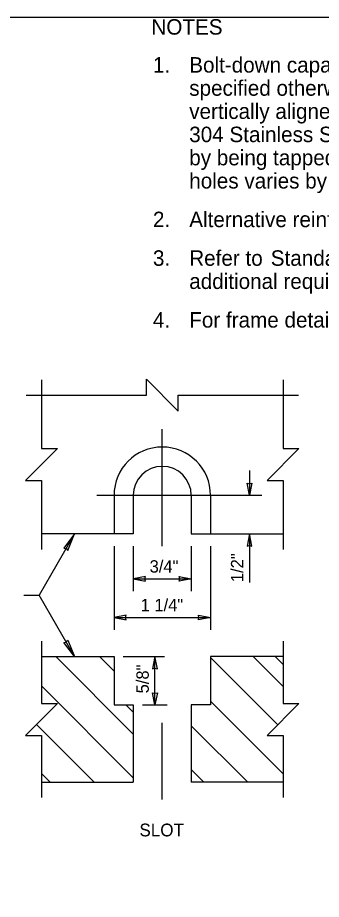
# Model space of a CAD drawing. Extents: x 99862 to 103151, y 100000 to 102076.
# Drawn here: x 101997 to 102390, y 100935 to 102076 of the extents above; entities that cross this region are included whole.
import ezdxf

# ---------------------------------------------------------------- set-up
doc = ezdxf.new("R2010")
doc.units = 0
for name, color, linetype in [('Level 1', 7, 'Continuous'), ('Level 15', 7, 'Continuous'), ('Level 17', 7, 'Continuous'), ('Level 2', 7, 'Continuous'), ('Level 20', 7, 'Continuous')]:
    doc.layers.add(name, color=color, linetype=linetype)

msp = doc.modelspace()

# ---------------------------------------------------------------- linework, layer by layer
at = {"layer": 'Level 1'}
msp.add_lwpolyline([(99862, 99999.5), (103151, 99999.5), (103151, 102075.5), (99862, 102075.5)], close=True, dxfattribs=at)
at = {"layer": 'Level 15'}
for p, q in [((102184.4, 101391.8), (102184.4, 101542.9)), ((102297.3, 101489.4), (102297.3, 101457.4)), ((102099.7, 101457.4), (102313.3, 101457.4)), ((102070.8, 101407.4), (102025, 101328.1)), ((102297.3, 101407.4), (102297.3, 101344.6)), ((102121.9, 101391.4), (102121.9, 101283.4)), ((102146.9, 101391.4), (102146.9, 101333.4)), ((102221.9, 101391.4), (102221.9, 101333.4)), ((102246.9, 101391.4), (102246.9, 101283.4)), ((102146.9, 101349.4), (102221.9, 101349.4)), ((102005, 101328.1), (102025, 101328.1)), ((102070.8, 101248.7), (102025, 101328.1)), ((102121.9, 101299.4), (102246.9, 101299.4)), ((102133.9, 101248.7), (102187.2, 101248.7)), ((102174.9, 101186.2), (102174.9, 101248.7)), ((102158.9, 101186.2), (102190.9, 101186.2)), ((102184.4, 101063.9), (102184.4, 101163.2))]:
    msp.add_line(p, q, dxfattribs=at)
for points in [[(102028.1, 101607), (102028.1, 101517.9), (102048.8, 101517.9), (102007.5, 101476.6), (102028.1, 101476.6), (102028.1, 101387.4)], [(102008.1, 101587), (102163.8, 101587), (102163.8, 101607.7), (102205.1, 101566.4), (102205.1, 101587), (102360.7, 101587)], [(102340.7, 101607), (102340.7, 101517.9), (102361.3, 101517.9), (102320, 101476.6), (102340.7, 101476.6), (102340.7, 101387.4)], [(102028.1, 101268.7), (102028.1, 101188.1), (102048.8, 101188.1), (102007.5, 101146.8), (102028.1, 101146.8), (102028.1, 101066.2)], [(102340.7, 101268.7), (102340.7, 101188.1), (102361.3, 101188.1), (102320, 101146.8), (102340.7, 101146.8), (102340.7, 101066.2)]]:
    msp.add_lwpolyline(points, dxfattribs=at)
for points in [[(102297.3, 101457.4), (102294.2, 101473.1), (102297.3, 101472.4), (102300.4, 101473.1)], [(102070.8, 101407.4), (102056.8, 101389.1), (102059.9, 101388.6), (102062, 101386.2)], [(102297.3, 101407.4), (102294.2, 101391.7), (102297.3, 101392.4), (102300.4, 101391.7)], [(102146.9, 101349.4), (102162.6, 101346.3), (102161.9, 101349.4), (102162.6, 101352.5)], [(102221.9, 101349.4), (102206.2, 101346.3), (102206.9, 101349.4), (102206.2, 101352.5)], [(102121.9, 101299.4), (102137.6, 101296.3), (102136.9, 101299.4), (102137.6, 101302.5)], [(102246.9, 101299.4), (102231.2, 101296.3), (102231.9, 101299.4), (102231.2, 101302.5)], [(102070.8, 101248.7), (102056.8, 101267), (102059.9, 101267.6), (102062, 101270)], [(102174.9, 101248.7), (102171.8, 101233), (102174.9, 101233.7), (102178, 101233)], [(102174.9, 101186.2), (102171.8, 101202), (102174.9, 101201.2), (102178, 101202)]]:
    msp.add_lwpolyline(points, close=True, dxfattribs=at)
at = {"layer": 'Level 17'}
for p, q in [((102146.9, 101148.5), (102046.6, 101248.7)), ((102121.9, 101230), (102103.2, 101248.7)), ((102333.8, 101160.6), (102246.9, 101247.4)), ((102340.7, 101210.2), (102302.2, 101248.7)), ((102340.7, 101238.5), (102330.4, 101248.7)), ((102146.9, 101091.9), (102028.1, 101210.7)), ((102340.7, 101097.1), (102246.9, 101190.9)), ((102146.9, 101176.8), (102137.4, 101186.2)), ((102096, 101086.2), (102021.5, 101160.8)), ((102295, 101086.2), (102221.9, 101159.3)), ((102039.4, 101086.2), (102028.1, 101097.5)), ((102238.4, 101086.2), (102221.9, 101102.7))]:
    msp.add_line(p, q, dxfattribs=at)
at = {"layer": 'Level 2'}
for p, q in [((102121.9, 101457.4), (102121.9, 101407.4)), ((102146.9, 101457.4), (102146.9, 101407.4)), ((102221.9, 101457.4), (102221.9, 101407.4)), ((102246.9, 101457.4), (102246.9, 101407.4)), ((102146.9, 101407.4), (102028.1, 101407.4)), ((102221.9, 101407.4), (102340.7, 101407.4)), ((102028.1, 101248.7), (102121.9, 101248.7)), ((102121.9, 101248.7), (102121.9, 101186.2)), ((102246.9, 101248.7), (102246.9, 101186.2)), ((102340.7, 101248.7), (102246.9, 101248.7)), ((102121.9, 101186.2), (102146.9, 101186.2)), ((102146.9, 101186.2), (102146.9, 101086.2)), ((102246.9, 101186.2), (102221.9, 101186.2)), ((102221.9, 101186.2), (102221.9, 101086.2)), ((102028.1, 101086.2), (102146.9, 101086.2)), ((102340.7, 101086.2), (102221.9, 101086.2))]:
    msp.add_line(p, q, dxfattribs=at)
for radius in [62.5, 37.5]:
    msp.add_arc((102184.4, 101457.4), radius, 360, 180, dxfattribs=at)

# ---------------------------------------------------------------- texts
at = {"layer": 'Level 1'}
msp.add_text('SLOT', height=16.5, dxfattribs=at).set_placement((102154.8, 101016.1))
at = {"layer": 'Level 20'}
for s, height, p in [('NOTES', 20, (102170.3, 102053.5)), ('1.', 20, (102172.3, 102004.4)), ('Bolt-down capability is required on all frames, grates, and covers, unless', 20, (102219.3, 102004.4)), ('specified otherwise in the Contract. Provide 2 holes in the frame that are', 20, (102219.3, 101974.4)), ('vertically aligned with the grate or cover slots. The frame shall accept the', 20, (102219.3, 101944.4)), ('304 Stainless Steel (S.S.) 5/8" (in) - 11 NC × 2" (in) allen head cap screw', 20, (102219.3, 101914.4)), ('by being tapped, or other approved mechanism. Location of bolt-down', 20, (102219.3, 101884.4)), ('holes varies by manufacturer.', 20, (102219.3, 101854.4)), ('2.', 20, (102172.3, 101804.4)), ('Alternative reinforcing designs are acceptable in lieu of the rib design.', 20, (102219.3, 101804.4)), ('3.', 20, (102172.3, 101754.4)), ('Refer to', 20, (102219.3, 101754.4)), (' Standard Specification Section 9-05.15', 20, (102317.4, 101754.4)), ('additional requirements.', 20, (102219.3, 101724.4)), ('4.', 20, (102172.3, 101674.4)), ('For frame details, see ', 20, (102219.3, 101674.4)), ('3/4"', 16, (102168, 101357.4)), ('1 1/4"', 16, (102156.3, 101307.4))]:
    msp.add_text(s, height=height, dxfattribs=at).set_placement(p)
for s, p in [('1/2"', (102289.3, 101345)), ('5/8"', (102166.9, 101201.1))]:
    msp.add_text(s, height=16, rotation=90, dxfattribs=at).set_placement(p)

doc.saveas('drawing.dxf')
